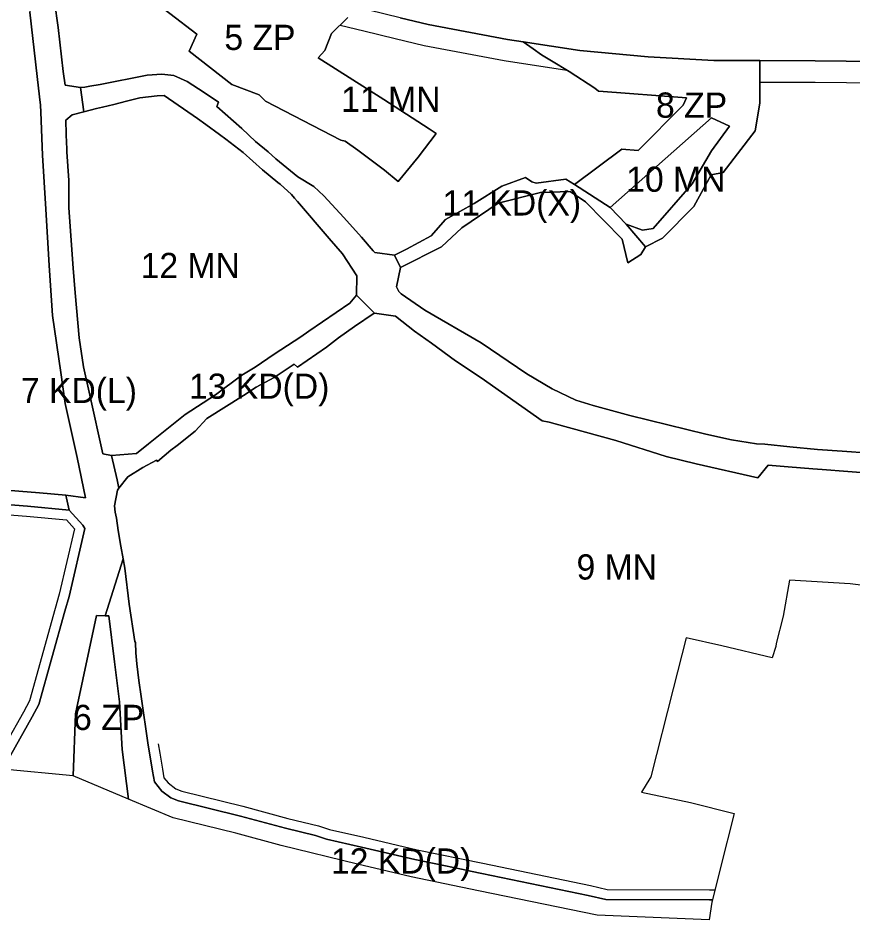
# Model space of a CAD drawing. Extents: x 7424258 to 7426021, y 5551671 to 5553193.
# Drawn here: x 7424679.4 to 7425010.8, y 5551690.7 to 5552048.8 of the extents above; entities that cross this region are included whole.
import ezdxf

# ---------------------------------------------------------------- set-up
doc = ezdxf.new("R2010")
doc.units = 0
for name, color, linetype in [('linie_rozgraniczajace', 7, 'Continuous'), ('linie_zabudowy_nieprzekraczalne', 7, 'Continuous'), ('oznaczenia_przeznaczen', 7, 'Continuous')]:
    doc.layers.add(name, color=color, linetype=linetype)

msp = doc.modelspace()

# ---------------------------------------------------------------- linework, layer by layer
at = {"layer": 'linie_rozgraniczajace'}
msp.add_line((7424955.09, 5551698.67), (7424954.88, 5551697.81), dxfattribs=at)
for points in [[(7425032.81, 5552031.43), (7424995.89, 5552031.74), (7424973.91, 5552031.84), (7424955.58, 5552031.92), (7424929.48, 5552033.35), (7424902.43, 5552035.87), (7424879.98, 5552039.33), (7424873.76, 5552040.29), (7424842.16, 5552046.19), (7424831.17, 5552048.83), (7424818.67, 5552051.92), (7424805.2, 5552055.23), (7424775.7, 5552063.16), (7424761.74, 5552067.05), (7424737.86, 5552074.72), (7424728.86, 5552078.21), (7424708.37, 5552086.04), (7424691.05, 5552093.06), (7424685.96, 5552087.72), (7424670.82, 5552093.85)], [(7424677.62, 5552074.88), (7424680.06, 5552073.64), (7424681.31, 5552071.2), (7424682.38, 5552065.45), (7424684.08, 5552051.04), (7424687.05, 5552025.56), (7424687.96, 5552017.41), (7424688.32, 5552014.2), (7424688.51, 5552011.44), (7424689.18, 5551994.38), (7424690.41, 5551972.83), (7424691.84, 5551950.51), (7424693.07, 5551930.65), (7424696.39, 5551908.08), (7424698.2, 5551895.73), (7424702.85, 5551874.25), (7424706.24, 5551858.3), (7424698.38, 5551859.38), (7424687.92, 5551860.23), (7424590.95, 5551868.06)], [(7424810.34, 5552048.98), (7424803.82, 5552042.57), (7424801.18, 5552035.81), (7424798.54, 5552032.97), (7424824.63, 5552016.43), (7424842.67, 5552004.74), (7424845.38, 5552002.92), (7424838.29, 5551993.46), (7424830.38, 5551983.87), (7424824.91, 5551988.31), (7424814.32, 5551996.27), (7424809.27, 5551999.81), (7424807.57, 5552000.33), (7424777.69, 5552015.75), (7424775.12, 5552018.3), (7424764.25, 5552022.42), (7424747.31, 5552035.63), (7424750.47, 5552042.38), (7424729, 5552058.86)], [(7424729, 5552058.86), (7424750.47, 5552042.38), (7424747.31, 5552035.63), (7424764.25, 5552022.42), (7424775.12, 5552018.3), (7424777.69, 5552015.75), (7424807.57, 5552000.33), (7424809.27, 5551999.81), (7424814.32, 5551996.27), (7424824.91, 5551988.31), (7424830.38, 5551983.87), (7424838.29, 5551993.46), (7424845.38, 5552002.92), (7424842.67, 5552004.74), (7424824.63, 5552016.43), (7424798.54, 5552032.97), (7424801.18, 5552035.81), (7424803.82, 5552042.57), (7424810.34, 5552048.98)], [(7424693.89, 5552055.37), (7424695.36, 5552045.03), (7424697.41, 5552027.53), (7424698.08, 5552022.1), (7424704.19, 5552021.15), (7424705.54, 5552011.53), (7424700.95, 5552010.38), (7424698.39, 5552008.26), (7424698.56, 5552002.64), (7424698.73, 5551999.15), (7424698.78, 5551997.12), (7424698.86, 5551995.59), (7424699.58, 5551984.21), (7424699.61, 5551973.42), (7424701.36, 5551949.42), (7424702.07, 5551939.67), (7424703.68, 5551921.74), (7424705.47, 5551910.28), (7424707.96, 5551898.99), (7424713.16, 5551875.81), (7424716.6, 5551875.15), (7424718.73, 5551865.46), (7424719.49, 5551862.14), (7424718.9, 5551861.39), (7424717.79, 5551855.17), (7424718, 5551852.66), (7424718.51, 5551850.23), (7424719.22, 5551845.29), (7424720.21, 5551839.16), (7424721.17, 5551834.13), (7424714.08, 5551811.46), (7424710.54, 5551811.59), (7424702.2, 5551772.58), (7424701.33, 5551747.93), (7424673.44, 5551750.52), (7424685.08, 5551771.37), (7424687.67, 5551776.27), (7424698.06, 5551813.34), (7424699.67, 5551819.11), (7424705.97, 5551846.15), (7424705.17, 5551847.38), (7424699.79, 5551853.42), (7424698.38, 5551859.38), (7424706.24, 5551858.3), (7424702.85, 5551874.25), (7424698.2, 5551895.73), (7424696.39, 5551908.08), (7424693.07, 5551930.65), (7424691.84, 5551950.51), (7424690.41, 5551972.83), (7424689.18, 5551994.38), (7424688.51, 5552011.44), (7424688.32, 5552014.2), (7424687.96, 5552017.41), (7424687.05, 5552025.56), (7424684.08, 5552051.04)], [(7424831.17, 5552048.83), (7424842.16, 5552046.19), (7424873.76, 5552040.29), (7424879.98, 5552039.33), (7424883.84, 5552036.57), (7424887.2, 5552034.17), (7424891.18, 5552031.75), (7424898.18, 5552027.51), (7424908.37, 5552020.87), (7424909.85, 5552019.73), (7424909.92, 5552019.68), (7424944.82, 5552017.11), (7424943.38, 5552014.14), (7424925.62, 5551996.16), (7424919.16, 5551996.76), (7424900.28, 5551982.61), (7424896.91, 5551984.77), (7424885.12, 5551983.17), (7424883.34, 5551983.74), (7424880.92, 5551985.43), (7424871.47, 5551982.03), (7424860.44, 5551975.12), (7424849.14, 5551968.77), (7424843.38, 5551962.35), (7424833.65, 5551956.95), (7424828.86, 5551954.62), (7424821.03, 5551955.73), (7424820.38, 5551956.39), (7424815.8, 5551961.72), (7424808.77, 5551969.62), (7424800.79, 5551978.23), (7424796.81, 5551981.92), (7424790.51, 5551985.74), (7424781.72, 5551992.85), (7424778.69, 5551995.65), (7424773.72, 5551999.72), (7424768.21, 5552004.84), (7424758.31, 5552013.57), (7424758.96, 5552015.4), (7424753.3, 5552019.16), (7424746.63, 5552023.61), (7424741.21, 5552025.99), (7424736.57, 5552026.51), (7424730.66, 5552026.02), (7424711.98, 5552022.42), (7424707.96, 5552021.77), (7424705.99, 5552021.36), (7424704.19, 5552021.15), (7424698.08, 5552022.1), (7424697.41, 5552027.53), (7424695.36, 5552045.03), (7424693.89, 5552055.37)], [(7425017.54, 5551875.99), (7425006.57, 5551876.8), (7424996.77, 5551877.52), (7424985.84, 5551878.59), (7424975.82, 5551879.58), (7424972.51, 5551879.73), (7424962.59, 5551881.28), (7424952.43, 5551883.55), (7424922.27, 5551890.94), (7424907.66, 5551894.97), (7424900.88, 5551897.12), (7424891.41, 5551901.57), (7424881.39, 5551907.55), (7424863.22, 5551919.87), (7424840.92, 5551932.83), (7424831.52, 5551939.24), (7424830.57, 5551940.19), (7424829.65, 5551942.04), (7424831.28, 5551949.69), (7424847.46, 5551957.91), (7424855.57, 5551965.53), (7424869.98, 5551975.26), (7424886.84, 5551979.51), (7424898.62, 5551979.89), (7424904.67, 5551975.83), (7424919.18, 5551960.95), (7424921.5, 5551951.54), (7424926.65, 5551954.92), (7424928.43, 5551957.97), (7424935.18, 5551961.43), (7424947.66, 5551973.88), (7424954.51, 5551986.46), (7424959.38, 5551987.41), (7424971.99, 5552003.99), (7424973.9, 5552014.95), (7424973.92, 5552024.81), (7424973.92, 5552026.84), (7424973.91, 5552031.84), (7424995.89, 5552031.74), (7425032.81, 5552031.43)], [(7424704.19, 5552021.15), (7424705.99, 5552021.36), (7424707.96, 5552021.77), (7424711.98, 5552022.42), (7424730.66, 5552026.02), (7424736.57, 5552026.51), (7424741.21, 5552025.99), (7424746.63, 5552023.61), (7424753.3, 5552019.16), (7424758.96, 5552015.4), (7424758.31, 5552013.57), (7424768.21, 5552004.84), (7424773.72, 5551999.72), (7424778.69, 5551995.65), (7424781.72, 5551992.85), (7424790.51, 5551985.74), (7424796.81, 5551981.92), (7424800.79, 5551978.23), (7424808.77, 5551969.62), (7424815.8, 5551961.72), (7424820.38, 5551956.39), (7424821.03, 5551955.73), (7424828.86, 5551954.62), (7424831.28, 5551949.69), (7424829.65, 5551942.04), (7424830.57, 5551940.19), (7424831.52, 5551939.24), (7424840.92, 5551932.83), (7424863.22, 5551919.87), (7424881.39, 5551907.55), (7424891.41, 5551901.57), (7424900.88, 5551897.12), (7424907.66, 5551894.97), (7424922.27, 5551890.94), (7424952.43, 5551883.55), (7424962.59, 5551881.28), (7424972.51, 5551879.73), (7424975.82, 5551879.58), (7424985.84, 5551878.59), (7424996.77, 5551877.52), (7425006.57, 5551876.8), (7425017.54, 5551875.99)], [(7425019.04, 5551867.93), (7424998.6, 5551869.48), (7424994.94, 5551869.75), (7424985.12, 5551870.65), (7424977.17, 5551871.29), (7424973.06, 5551866.21), (7424948.65, 5551871.73), (7424936.67, 5551874.72), (7424916.67, 5551881.01), (7424892.69, 5551887.63), (7424890.25, 5551888.35), (7424887.47, 5551888.89), (7424863.29, 5551905.98), (7424853.04, 5551912.71), (7424843.61, 5551919.7), (7424836.86, 5551924.48), (7424829.21, 5551930.37), (7424820.88, 5551931.62), (7424813.83, 5551938.75), (7424813.89, 5551946.45), (7424808.17, 5551955.14), (7424802.96, 5551961.2), (7424790.34, 5551975.87), (7424789.14, 5551977.27), (7424787.94, 5551978.68), (7424783.45, 5551982.77), (7424782.55, 5551983.5), (7424776.48, 5551988.43), (7424768.76, 5551995.39), (7424761.96, 5552000.62), (7424759.36, 5552002.48), (7424754.01, 5552006.44), (7424750.68, 5552008.91), (7424737.46, 5552017.96), (7424734.65, 5552017.91), (7424727.72, 5552017.04), (7424722.47, 5552015.74), (7424717.43, 5552014.48), (7424712.95, 5552013.37), (7424710.58, 5552012.79), (7424705.54, 5552011.53), (7424704.19, 5552021.15)], [(7424719.49, 5551862.14), (7424722.99, 5551866.6), (7424728.93, 5551870.38), (7424734.35, 5551873.27), (7424734.76, 5551872.65), (7424740.04, 5551877.16), (7424742.55, 5551879.07), (7424749.77, 5551884.8), (7424754.43, 5551889.79), (7424768.99, 5551898.93), (7424774.02, 5551902.22), (7424781.1, 5551906.12), (7424789.02, 5551911.39), (7424790.42, 5551910.1), (7424801.88, 5551918.15), (7424806.64, 5551921.85), (7424812.93, 5551926.33), (7424820.84, 5551931.6), (7424820.88, 5551931.62), (7424829.21, 5551930.37), (7424836.86, 5551924.48), (7424843.61, 5551919.7), (7424853.04, 5551912.71), (7424863.29, 5551905.98), (7424887.47, 5551888.89), (7424890.25, 5551888.35), (7424892.69, 5551887.63), (7424916.67, 5551881.01), (7424936.67, 5551874.72), (7424948.65, 5551871.73), (7424973.06, 5551866.21), (7424977.17, 5551871.29), (7424985.12, 5551870.65), (7424994.94, 5551869.75), (7424998.6, 5551869.48), (7425019.04, 5551867.93)], [(7424590.95, 5551868.06), (7424687.92, 5551860.23), (7424698.38, 5551859.38), (7424699.79, 5551853.42), (7424683.16, 5551854.93), (7424589.9, 5551862.39)], [(7424589.9, 5551862.39), (7424683.16, 5551854.93), (7424699.79, 5551853.42), (7424705.17, 5551847.38), (7424705.97, 5551846.15), (7424699.67, 5551819.11), (7424698.06, 5551813.34), (7424687.67, 5551776.27), (7424685.08, 5551771.37), (7424673.44, 5551750.52)], [(7424955.09, 5551698.67), (7424953.87, 5551698.72), (7424912.78, 5551698.78), (7424905.78, 5551700.43), (7424863.59, 5551709.18), (7424859.02, 5551710.13), (7424856.14, 5551710.73), (7424836.95, 5551714.7), (7424815.78, 5551719.65), (7424801.93, 5551722.74), (7424797.54, 5551724.25), (7424785.58, 5551727.12), (7424767.69, 5551731.98), (7424743.17, 5551738), (7424740.12, 5551739.26), (7424736.49, 5551741.86), (7424733.58, 5551745.49), (7424732.83, 5551749.84), (7424731.71, 5551756.3), (7424731.14, 5551760.12), (7424728.27, 5551779.38), (7424727.39, 5551785.73), (7424726.62, 5551792.42), (7424726.24, 5551796.8), (7424726.06, 5551800.9), (7424725.73, 5551801.2), (7424723.5, 5551816.03), (7424721.89, 5551830.36), (7424721.17, 5551834.13), (7424720.21, 5551839.16), (7424719.22, 5551845.29), (7424718.51, 5551850.23), (7424718, 5551852.66), (7424717.79, 5551855.17), (7424718.9, 5551861.39), (7424719.49, 5551862.14)], [(7424953.7, 5551690.72), (7424909.24, 5551692.56), (7424862.17, 5551702.32), (7424835.44, 5551707.86), (7424814.21, 5551712.82), (7424783.85, 5551720.33), (7424765.93, 5551725.2), (7424740.98, 5551731.32), (7424723.28, 5551738.7), (7424720.83, 5551758.34), (7424719.77, 5551777.33), (7424717.72, 5551793.24), (7424715.51, 5551811.41), (7424714.08, 5551811.46), (7424721.17, 5551834.13), (7424721.89, 5551830.36), (7424723.5, 5551816.03), (7424725.73, 5551801.2), (7424726.06, 5551800.9), (7424726.24, 5551796.8), (7424726.62, 5551792.42), (7424727.39, 5551785.73), (7424728.27, 5551779.38), (7424731.14, 5551760.12), (7424731.71, 5551756.3), (7424732.83, 5551749.84), (7424733.58, 5551745.49), (7424736.49, 5551741.86), (7424740.12, 5551739.26), (7424743.17, 5551738), (7424767.69, 5551731.98), (7424785.58, 5551727.12), (7424797.54, 5551724.25), (7424801.93, 5551722.74), (7424815.78, 5551719.65), (7424836.95, 5551714.7), (7424856.14, 5551710.73), (7424859.02, 5551710.13), (7424863.59, 5551709.18), (7424905.78, 5551700.43), (7424912.78, 5551698.78), (7424953.87, 5551698.72), (7424955.09, 5551698.67)], [(7425032.31, 5551822.76), (7425020.77, 5551823.55), (7425012.91, 5551823.76), (7425009.66, 5551824.12), (7424985.59, 5551825.62), (7424983.07, 5551811.29), (7424980.32, 5551800.43), (7424980.26, 5551799.25), (7424978.71, 5551794.76), (7424958.8, 5551799.48), (7424944.69, 5551802.76), (7424939.44, 5551782.44), (7424930.64, 5551747.51), (7424930.26, 5551746.88)], [(7424930.26, 5551746.88), (7424926.93, 5551741.46), (7424946.31, 5551737.32), (7424963.63, 5551733.04)], [(7424963.63, 5551733.04), (7424958.27, 5551711.5), (7424955.09, 5551698.67)], [(7424954.88, 5551697.81), (7424953.7, 5551690.72)]]:
    msp.add_lwpolyline(points, dxfattribs=at)
for points in [[(7424879.98, 5552039.33), (7424902.43, 5552035.87), (7424929.48, 5552033.35), (7424955.58, 5552031.92), (7424973.91, 5552031.84), (7424973.92, 5552026.84), (7424973.92, 5552024.81), (7424973.9, 5552014.95), (7424971.99, 5552003.99), (7424959.38, 5551987.41), (7424954.51, 5551986.46), (7424947.66, 5551973.88), (7424935.18, 5551961.43), (7424928.43, 5551957.97), (7424920.8, 5551966.92), (7424927.35, 5551964.57), (7424931.51, 5551965.14), (7424946.97, 5551982.98), (7424954.69, 5551995.99), (7424961.83, 5552005.77), (7424954.65, 5552009.09), (7424914.47, 5551973.55), (7424900.28, 5551982.61), (7424919.16, 5551996.76), (7424925.62, 5551996.16), (7424943.38, 5552014.14), (7424944.82, 5552017.11), (7424909.92, 5552019.68), (7424909.85, 5552019.73), (7424908.37, 5552020.87), (7424898.18, 5552027.51), (7424891.18, 5552031.75), (7424887.2, 5552034.17), (7424883.84, 5552036.57)], [(7424705.54, 5552011.53), (7424710.58, 5552012.79), (7424712.95, 5552013.37), (7424717.43, 5552014.48), (7424722.47, 5552015.74), (7424727.72, 5552017.04), (7424734.65, 5552017.91), (7424737.46, 5552017.96), (7424750.68, 5552008.91), (7424754.01, 5552006.44), (7424759.36, 5552002.48), (7424761.96, 5552000.62), (7424768.76, 5551995.39), (7424776.48, 5551988.43), (7424782.55, 5551983.5), (7424783.45, 5551982.77), (7424787.94, 5551978.68), (7424789.14, 5551977.27), (7424790.34, 5551975.87), (7424802.96, 5551961.2), (7424808.17, 5551955.14), (7424813.89, 5551946.45), (7424813.83, 5551938.75), (7424811.15, 5551935.57), (7424794.87, 5551924.39), (7424791.7, 5551922.24), (7424781.13, 5551915.3), (7424773.55, 5551910.17), (7424768.31, 5551907), (7424757.79, 5551899.19), (7424745.83, 5551891.34), (7424731.21, 5551879.73), (7424726.45, 5551875.94), (7424716.6, 5551875.15), (7424713.16, 5551875.81), (7424707.96, 5551898.99), (7424705.47, 5551910.28), (7424703.68, 5551921.74), (7424702.07, 5551939.67), (7424701.36, 5551949.42), (7424699.61, 5551973.42), (7424699.58, 5551984.21), (7424698.86, 5551995.59), (7424698.78, 5551997.12), (7424698.73, 5551999.15), (7424698.56, 5552002.64), (7424698.39, 5552008.26), (7424700.95, 5552010.38)], [(7424914.47, 5551973.55), (7424954.65, 5552009.09), (7424961.83, 5552005.77), (7424954.69, 5551995.99), (7424946.97, 5551982.98), (7424931.51, 5551965.14), (7424927.35, 5551964.57), (7424920.8, 5551966.92)], [(7424828.86, 5551954.62), (7424833.65, 5551956.95), (7424843.38, 5551962.35), (7424849.14, 5551968.77), (7424860.44, 5551975.12), (7424871.47, 5551982.03), (7424880.92, 5551985.43), (7424883.34, 5551983.74), (7424885.12, 5551983.17), (7424896.91, 5551984.77), (7424900.28, 5551982.61), (7424914.47, 5551973.55), (7424920.8, 5551966.92), (7424928.43, 5551957.97), (7424926.65, 5551954.92), (7424921.5, 5551951.54), (7424919.18, 5551960.95), (7424904.67, 5551975.83), (7424898.62, 5551979.89), (7424886.84, 5551979.51), (7424869.98, 5551975.26), (7424855.57, 5551965.53), (7424847.46, 5551957.91), (7424831.28, 5551949.69)], [(7424716.6, 5551875.15), (7424726.45, 5551875.94), (7424731.21, 5551879.73), (7424745.83, 5551891.34), (7424757.79, 5551899.19), (7424768.31, 5551907), (7424773.55, 5551910.17), (7424781.13, 5551915.3), (7424791.7, 5551922.24), (7424794.87, 5551924.39), (7424811.15, 5551935.57), (7424813.83, 5551938.75), (7424820.88, 5551931.62), (7424820.84, 5551931.6), (7424812.93, 5551926.33), (7424806.64, 5551921.85), (7424801.88, 5551918.15), (7424790.42, 5551910.1), (7424789.02, 5551911.39), (7424781.1, 5551906.12), (7424774.02, 5551902.22), (7424768.99, 5551898.93), (7424754.43, 5551889.79), (7424749.77, 5551884.8), (7424742.55, 5551879.07), (7424740.04, 5551877.16), (7424734.76, 5551872.65), (7424734.35, 5551873.27), (7424728.93, 5551870.38), (7424722.99, 5551866.6), (7424719.49, 5551862.14), (7424718.73, 5551865.46)], [(7424701.33, 5551747.93), (7424702.2, 5551772.58), (7424710.54, 5551811.59), (7424714.08, 5551811.46), (7424715.51, 5551811.41), (7424717.72, 5551793.24), (7424719.77, 5551777.33), (7424720.83, 5551758.34), (7424723.28, 5551738.7)]]:
    msp.add_lwpolyline(points, close=True, dxfattribs=at)
at = {"layer": 'linie_zabudowy_nieprzekraczalne'}
for points in [[(7424807.28, 5552045.97), (7424816.63, 5552043.67), (7424829.16, 5552040.57), (7424840.6, 5552037.84), (7424872.33, 5552031.91), (7424897.27, 5552028.07)], [(7424973.91, 5552023.34), (7424995.83, 5552023.24), (7425032.95, 5552022.93), (7425058.16, 5552023.96), (7425092.42, 5552027.42), (7425129.9, 5552032.84), (7425150.98, 5552037.86)], [(7424529.36, 5551863.37), (7424558.49, 5551860.97), (7424589.57, 5551858.4), (7424682.82, 5551850.95), (7424698.68, 5551849.5), (7424701.82, 5551845.97), (7424695.79, 5551820.11), (7424694.21, 5551814.42), (7424683.94, 5551777.76), (7424681.57, 5551773.27), (7424674.58, 5551760.77)], [(7424735.1, 5551760.7), (7424735.66, 5551756.93), (7424736.77, 5551750.52), (7424737.34, 5551747.19), (7424738.97, 5551745.16), (7424742.13, 5551742.76), (7424744.42, 5551741.8), (7424768.69, 5551735.85), (7424786.57, 5551730.99), (7424798.66, 5551728.1), (7424803.03, 5551726.59), (7424816.67, 5551723.54), (7424837.81, 5551718.61), (7424863.89, 5551713.2), (7424906.64, 5551704.34), (7424913.24, 5551702.78), (7424953.95, 5551702.71), (7424956.07, 5551702.62)]]:
    msp.add_lwpolyline(points, dxfattribs=at)

# ---------------------------------------------------------------- texts
at = {"layer": 'oznaczenia_przeznaczen'}
for s, p in [('5 ZP', (7424761.33, 5552036.07)), ('11 MN', (7424807.72, 5552011.51)), ('8 ZP', (7424932.65, 5552009.19)), ('10 MN', (7424920.83, 5551979.77)), ('11 KD(X)', (7424847.93, 5551970.36)), ('12 MN', (7424728.11, 5551945.53)), ('13 KD(D)', (7424747.29, 5551897.61)), ('7 KD(L)', (7424680.57, 5551895.89)), ('9 MN', (7424901.11, 5551825.85)), ('6 ZP', (7424701.27, 5551766.12)), ('12 KD(D)', (7424803.64, 5551709.13))]:
    msp.add_text(s, height=10, dxfattribs=at).set_placement(p)

doc.saveas('drawing.dxf')
